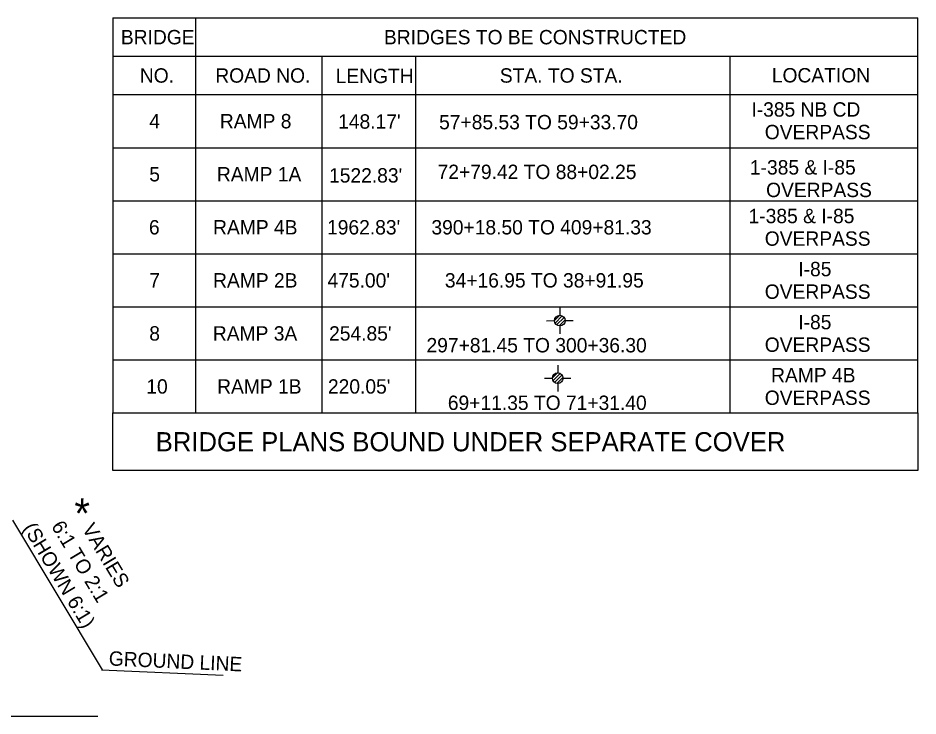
# Model space of a CAD drawing. Extents: x 4932 to 5887, y 4809 to 5473.
# Drawn here: x 5121 to 5196.1, y 5057.9 to 5116.2 of the extents above; entities that cross this region are included whole.
import ezdxf

# ---------------------------------------------------------------- set-up
doc = ezdxf.new("R2010")
doc.units = 0
for name, color, linetype in [('Level 3', 7, 'Continuous'), ('Level 42', 7, 'Continuous'), ('RD_EX_SU_Pole', 7, 'Continuous'), ('RD_SHT_Typical', 7, 'Continuous'), ('RD_TX_TitleSht', 7, 'Continuous'), ('RD_TX_TypSect', 7, 'Continuous'), ('RD_XS_ExGround', 7, 'Continuous')]:
    doc.layers.add(name, color=color, linetype=linetype)

# ---------------------------------------------------------------- blocks, each defined once
blk = doc.blocks.new('SUE_TFP')
at = {"layer": 'RD_EX_SU_Pole'}
for p, q in [((0, 5.5), (0, 2.22)), ((-2.21, 0.13), (-0.13, 2.21)), ((-1.96, -1.03), (1.03, 1.96)), ((-1.31, -1.79), (1.79, 1.31)), ((-0.3, -2.2), (2.2, 0.3)), ((2.22, 0), (5.53, 0.01)), ((-5.53, -0.01), (-2.22, 0)), ((0, -2.22), (0, -5.5))]:
    blk.add_line(p, q, dxfattribs=at)
blk.add_circle((0, 0), 2.22, dxfattribs=at)

msp = doc.modelspace()

# ---------------------------------------------------------------- linework, layer by layer
at = {"layer": 'Level 3'}
for p, q in [((5128.915, 5116.224), (5196.115, 5116.224)), ((5135.844, 5083.246), (5135.844, 5116.224)), ((5196.115, 5083.246), (5196.115, 5116.224)), ((5128.915, 5113.024), (5196.115, 5113.024)), ((5146.398, 5083.246), (5146.398, 5113.024)), ((5154.195, 5083.246), (5154.195, 5113.024)), ((5180.435, 5083.246), (5180.435, 5113.024)), ((5128.915, 5109.824), (5196.115, 5109.824)), ((5128.915, 5083.246), (5196.115, 5083.246))]:
    msp.add_line(p, q, dxfattribs=at)
at = {"layer": 'Level 42'}
msp.add_lwpolyline([(5128.915, 5083.246), (5196.115, 5083.246), (5196.115, 5078.446), (5128.915, 5078.446)], close=True, dxfattribs=at)
at = {"layer": 'RD_SHT_Typical'}
msp.add_line((5120.536, 5074.291), (5128.024, 5061.81), dxfattribs=at)
at = {"layer": 'RD_TX_TitleSht'}
msp.add_line((5128.915, 5116.224), (5128.915, 5083.246), dxfattribs=at)
at = {"layer": 'RD_TX_TypSect'}
for p, q in [((5128.915, 5105.394), (5196.115, 5105.394)), ((5128.915, 5100.964), (5196.115, 5100.964)), ((5128.915, 5096.535), (5196.115, 5096.535)), ((5128.915, 5092.105), (5196.115, 5092.105)), ((5128.915, 5087.676), (5196.115, 5087.676)), ((5069.292, 5057.946), (5127.661, 5057.946))]:
    msp.add_line(p, q, dxfattribs=at)
at = {"layer": 'RD_XS_ExGround'}
msp.add_line((5127.984, 5061.812), (5138.134, 5061.349), dxfattribs=at)

# ---------------------------------------------------------------- block references
at = {"layer": 'Level 3', "xscale": 0.19999999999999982, "yscale": 0.19999999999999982}
for p in [(5166.22, 5090.955), (5166.045, 5086.148)]:
    msp.add_blockref('SUE_TFP', p, dxfattribs=at)

# ---------------------------------------------------------------- texts
at = {"layer": 'Level 3'}
for s, height, p in [('BRIDGE', 1.2, (5129.591, 5114.024)), ('BRIDGES TO BE CONSTRUCTED', 1.2, (5151.546, 5114.024)), ('NO.', 1.2, (5131.174, 5110.824)), ('ROAD NO.', 1.2, (5137.471, 5110.824)), ('LENGTH', 1.2, (5147.512, 5110.786)), ('STA. TO STA.', 1.2, (5161.216, 5110.824)), ('LOCATION', 1.2, (5183.915, 5110.844)), ('I-385 NB CD', 1.2, (5182.212, 5107.987)), ('RAMP 8', 1.2, (5137.852, 5107.009)), ('4', 1.2, (5131.961, 5107.009)), ("148.17'", 1.2, (5147.723, 5106.983)), ('57+85.53 TO 59+33.70', 1.2, (5156.149, 5106.929)), ('OVERPASS', 1.2, (5183.327, 5106.101)), ('5', 1.2, (5131.961, 5102.579)), ('RAMP 1A', 1.2, (5137.606, 5102.579)), ('72+79.42 TO 88+02.25', 1.2, (5156.023, 5102.777)), ('1-385 & I-85 ', 1.2, (5182.087, 5103.154)), ("1522.83'", 1.2, (5146.964, 5102.484)), ('OVERPASS', 1.2, (5183.438, 5101.268)), ('1-385 & I-85 ', 1.2, (5181.976, 5099.092)), ('6', 1.2, (5131.933, 5098.15)), ('RAMP 4B', 1.2, (5137.285, 5098.15)), ("1962.83'", 1.2, (5146.797, 5098.15)), ('390+18.50 TO 409+81.33', 1.2, (5155.507, 5098.15)), ('OVERPASS', 1.2, (5183.327, 5097.207)), ('I-85 ', 1.2, (5186.124, 5094.663)), ('7', 1.2, (5131.961, 5093.72)), ('RAMP 2B', 1.2, (5137.285, 5093.72)), ("475.00'", 1.2, (5146.835, 5093.72)), ('34+16.95 TO 38+91.95', 1.2, (5156.631, 5093.72)), ('OVERPASS', 1.2, (5183.327, 5092.777)), ('I-85 ', 1.2, (5186.124, 5090.233)), ('8', 1.2, (5131.961, 5089.29)), ('RAMP 3A', 1.2, (5137.266, 5089.29)), ("254.85'", 1.2, (5146.967, 5089.29)), ('297+81.45 TO 300+36.30', 1.2, (5155.096, 5088.305)), ('OVERPASS', 1.2, (5183.327, 5088.348)), ('RAMP 4B ', 1.2, (5183.856, 5085.804)), ('10', 1.2, (5131.715, 5084.861)), ('RAMP 1B', 1.2, (5137.625, 5084.861)), ("220.05'", 1.2, (5146.872, 5084.861)), ('OVERPASS', 1.2, (5183.327, 5083.918)), ('69+11.35 TO 71+31.40', 1.2, (5156.877, 5083.498)), ('BRIDGE PLANS BOUND UNDER SEPARATE COVER', 1.6, (5132.499, 5080.046))]:
    msp.add_text(s, height=height, rotation=360, dxfattribs=at).set_placement(p)
at = {"layer": 'RD_TX_TypSect'}
msp.add_text('*', height=2.5, dxfattribs=at).set_placement((5125.709, 5073.62))
for s, rotation, p in [('(SHOWN 6:1)', 300.96376, (5121.389, 5073.642)), ('6:1 TO 2:1', 300.96376, (5123.744, 5073.799)), ('VARIES', 300.96376, (5126.32, 5073.587)), ('GROUND LINE', 357.39046, (5128.561, 5062.17))]:
    msp.add_text(s, height=1.2, rotation=rotation, dxfattribs=at).set_placement(p)

doc.saveas('drawing.dxf')
